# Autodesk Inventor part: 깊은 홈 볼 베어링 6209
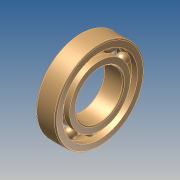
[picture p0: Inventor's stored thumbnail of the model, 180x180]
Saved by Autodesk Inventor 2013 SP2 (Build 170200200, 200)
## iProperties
Created: 2025-06
Part Number: 깊은 홈 볼 베어링 6209
Material: Generic
Document SubType Name: Modeling
Designer: i
Density: 1 g/cm^3
Author: i
변환 표준: STEP AP214IS
전처리기: Build: 200, Release: 2013 SP2 Update 6 - Date: Thu 07/17/2014
전송 단위: 밀리미터
불확실성: 0.01
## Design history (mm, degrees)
node "깊은 홈 볼 베어링 62091"
body "Solid1"
node "Solid1_1"
node "Solid1_2"
node "Solid1_3"
node "Solid1_4"
node "Solid1_5"
node "Solid1_6"
node "Solid1_7"
node "Solid1_8"
node "Solid1_9"
node "Solid1_10"
node "Solid1_11"
node "기준1"
node "기준2"
node "기준3"
node "기준4"
node "기준5"
node "기준6"
node "기준7"
node "기준8"
node "기준9"
node "기준10"
node "기준11"
node "기준12"
